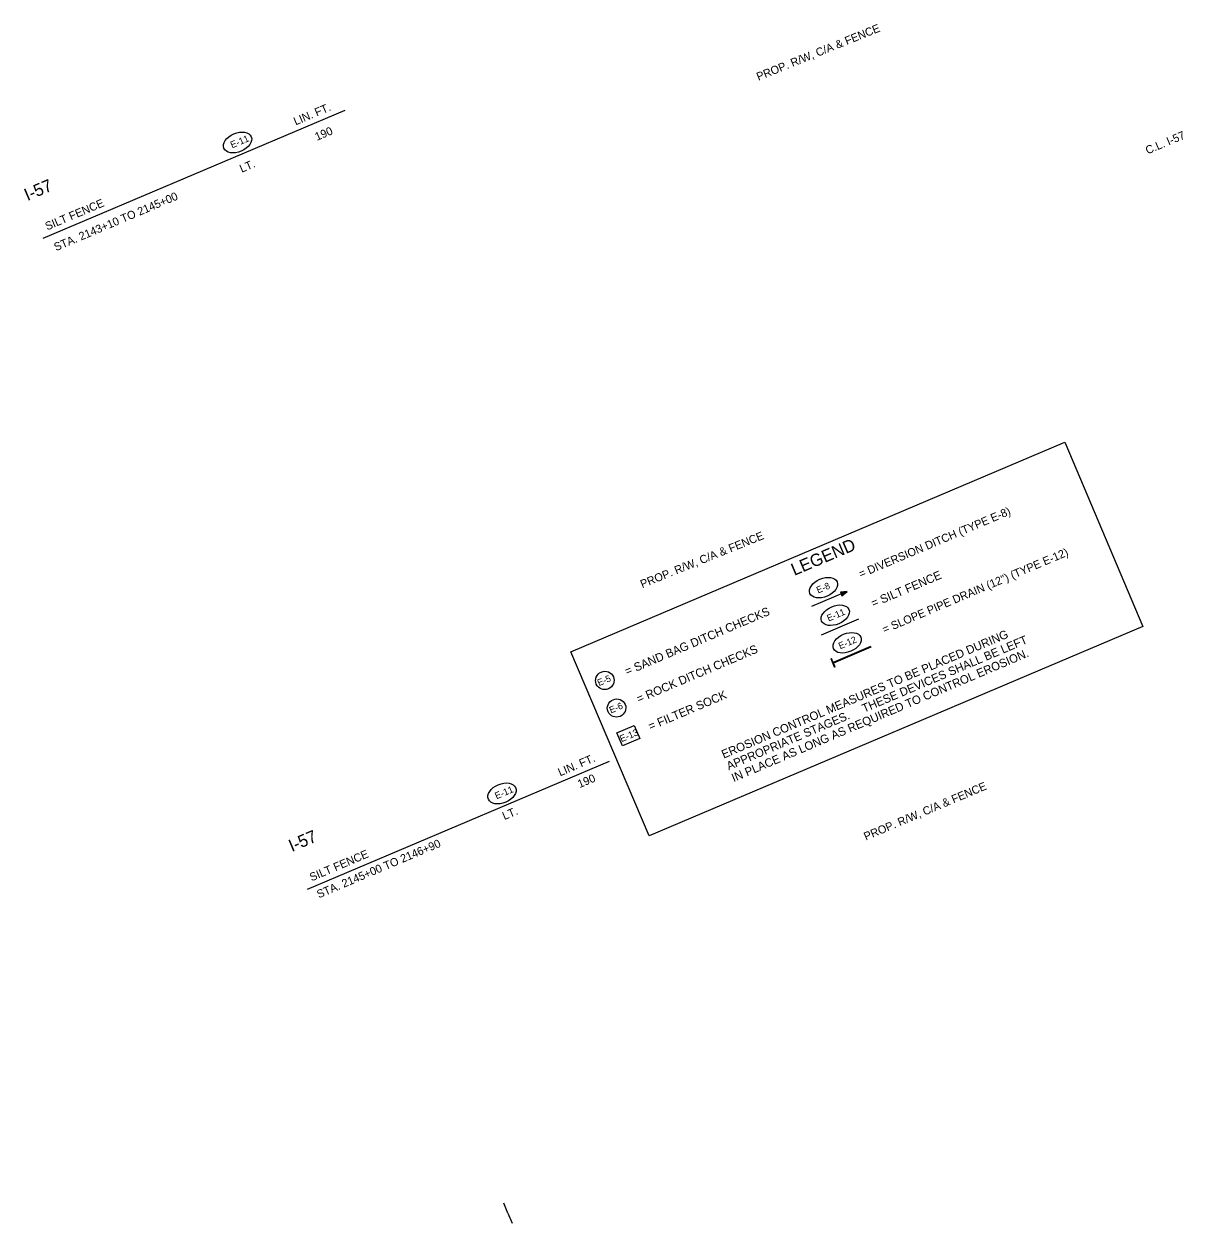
# Model space of a CAD drawing. Extents: x 1718863 to 1720683, y 766511 to 767857.
# Drawn here: x 1718863 to 1719720, y 766511 to 767398 of the extents above; entities that cross this region are included whole.
import ezdxf

# ---------------------------------------------------------------- set-up
doc = ezdxf.new("R2010")
doc.units = 0
for name, color, linetype in [('1', 7, 'Continuous'), ('44', 7, 'Continuous'), ('Default', 7, 'Continuous'), ('Level 1', 7, 'Continuous'), ('Level 44', 7, 'Continuous'), ('R_Draft', 7, 'Continuous')]:
    doc.layers.add(name, color=color, linetype=linetype)

msp = doc.modelspace()

# ---------------------------------------------------------------- linework, layer by layer
at = {"layer": '1'}
for points in [[(1719267.4, 766933.74), (1719632.56, 767088.66), (1719690.32, 766952.51), (1719325.17, 766797.59)], [(1719301.31, 766873.79), (1719314.22, 766879.27), (1719318.33, 766869.6), (1719305.42, 766864.12)]]:
    msp.add_lwpolyline(points, close=True, dxfattribs=at)
for centre in [(1719020.84, 767310.39), (1719216.38, 766829.01)]:
    msp.add_ellipse(centre, major_axis=(10.09, 4.28), ratio=0.638788, dxfattribs=at)
at = {"layer": '44'}
for p, q in [((1718877.09, 767239.54), (1719100.33, 767334.25)), ((1719072.63, 766758.16), (1719295.87, 766852.87))]:
    msp.add_line(p, q, dxfattribs=at)
at = {"layer": 'Default'}
for q in [(1719217.67, 766526.12), (1719223.79, 766511.33)]:
    msp.add_line((1719220.73, 766518.72), q, dxfattribs=at)
at = {"layer": 'Level 1'}
for p, q in [((1719471.56, 766978.44), (1719466.57, 766977.89)), ((1719466.57, 766977.89), (1719467.7, 766975.24)), ((1719470.3, 766978.22), (1719466.72, 766977.57)), ((1719470.32, 766978.13), (1719466.86, 766977.23)), ((1719470.34, 766978.03), (1719467, 766976.91)), ((1719467.28, 766976.23), (1719470.43, 766977.86)), ((1719467.42, 766975.91), (1719470.46, 766977.78)), ((1719467.56, 766975.57), (1719470.52, 766977.7)), ((1719467.7, 766975.24), (1719471.56, 766978.44))]:
    msp.add_line(p, q, dxfattribs=at)
msp.add_lwpolyline([(1719445.61, 766967.44), (1719470, 766977.79)], dxfattribs=at)
for centre, major_axis, ratio in [((1719454.16, 766981.2), (10.09, 4.28), 0.622952), ((1719462.84, 766960.79), (10.08, 4.29), 0.622952), ((1719471.63, 766940.41), (10.09, 4.28), 0.622952), ((1719292.43, 766912.58), (-6.33, -2.69), 0.97521), ((1719301.11, 766892.17), (-6.33, -2.69), 0.97521)]:
    msp.add_ellipse(centre, major_axis=major_axis, ratio=ratio, dxfattribs=at)
at = {"layer": 'Level 44'}
for p, q in [((1719488.84, 766937.58), (1719461.35, 766925.91)), ((1719489.04, 766937.12), (1719461.54, 766925.45)), ((1719488.84, 766937.58), (1719489.04, 766937.12)), ((1719459.67, 766928.58), (1719460.13, 766928.77)), ((1719462.3, 766922.39), (1719459.67, 766928.58)), ((1719461.35, 766925.91), (1719460.13, 766928.77)), ((1719462.76, 766922.59), (1719461.54, 766925.45)), ((1719462.3, 766922.39), (1719462.76, 766922.59))]:
    msp.add_line(p, q, dxfattribs=at)
msp.add_lwpolyline([(1719452.64, 766946.31), (1719480.35, 766958.11)], dxfattribs=at)

# ---------------------------------------------------------------- texts
at = {"layer": '1'}
for s, rotation, p in [('E-11', 22.9899, (1719016.81, 767306.01)), ('E-13', 22.60764, (1719304.69, 766866.85)), ('E-11', 22.9899, (1719212.35, 766824.63))]:
    msp.add_text(s, height=4.999, rotation=rotation, dxfattribs=at).set_placement(p)
at = {"layer": '44'}
for s, p in [('LIN. FT.', (1719063.78, 767322.99)), ('190', (1719079.54, 767311.56)), ('LT.', (1719023.89, 767287.95)), ('STA. 2143+10 TO 2145+00', (1718886.58, 767229.96)), ('SILT FENCE      ', (1718880.06, 767245.32)), ('LIN. FT.', (1719259.32, 766841.61)), ('190', (1719273.78, 766832.89)), ('LT.', (1719218.13, 766809.28)), ('STA. 2145+00 TO 2146+90', (1719080.95, 766751.35)), ('SILT FENCE      ', (1719075.61, 766763.94))]:
    msp.add_text(s, height=6, rotation=22.9899, dxfattribs=at).set_placement(p)
at = {"layer": 'Level 1'}
for s, height, rotation, p in [('= DIVERSION DITCH (TYPE E-8)', 6, 22.98991, (1719481.72, 766988.27)), ('= SLOPE PIPE DRAIN (12") (TYPE E-12)', 6, 22.98991, (1719499.15, 766947.19)), ('= SILT FENCE', 6.25, 23.0479, (1719490.97, 766966.48)), ('E-8', 4.876, 22.98991, (1719450.13, 766976.84)), ('= SAND BAG DITCH CHECKS', 6.25, 23.0479, (1719308.86, 766916.17)), ('E-11 ', 4.876, 23.0479, (1719457.9, 766956.08)), ('EROSION CONTROL MEASURES TO BE PLACED DURING', 6.25, 23.0479, (1719380.35, 766854.71)), ('E-12', 4.876, 22.98991, (1719466.44, 766935.58)), ('THESE DEVICES SHALL BE LEFT', 6.25, 23.0479, (1719484.2, 766888.67)), ('= ROCK DITCH CHECKS', 6.25, 23.0479, (1719317.54, 766895.77)), ('IN PLACE AS LONG AS REQUIRED TO CONTROL EROSION.', 6.25, 23.0479, (1719387.72, 766837.39)), ('E-5 ', 4.876, 23.0479, (1719288.11, 766908.33)), ('= FILTER SOCK', 6.25, 22.98991, (1719326.15, 766875.46)), ('E-6 ', 4.876, 23.0479, (1719296.95, 766888.09)), ('APPROPRIATE STAGES. ', 6.25, 23.0479, (1719384.03, 766846.05))]:
    msp.add_text(s, height=height, rotation=rotation, dxfattribs=at).set_placement(p)
at = {"layer": 'Level 44'}
for s, rotation, p in [('I-57', 22.98991, (1718865.44, 767267.01)), ('LEGEND', 23.0479, (1719432.54, 766989.86)), ('I-57', 22.98991, (1719060.98, 766785.63))]:
    msp.add_text(s, height=9.143, rotation=rotation, dxfattribs=at).set_placement(p)
at = {"layer": 'R_Draft'}
for s, rotation, p in [('PROP. R/W, C/A & FENCE', 22.04919, (1719406.03, 767356.01)), ('C.L. I-57', 23, (1719693.76, 767301.53)), ('PROP. R/W, C/A & FENCE', 22.04919, (1719320.11, 766980.74)), ('PROP. R/W, C/A & FENCE', 23, (1719485.46, 766794.1))]:
    msp.add_text(s, height=6, rotation=rotation, dxfattribs=at).set_placement(p)

doc.saveas('drawing.dxf')
